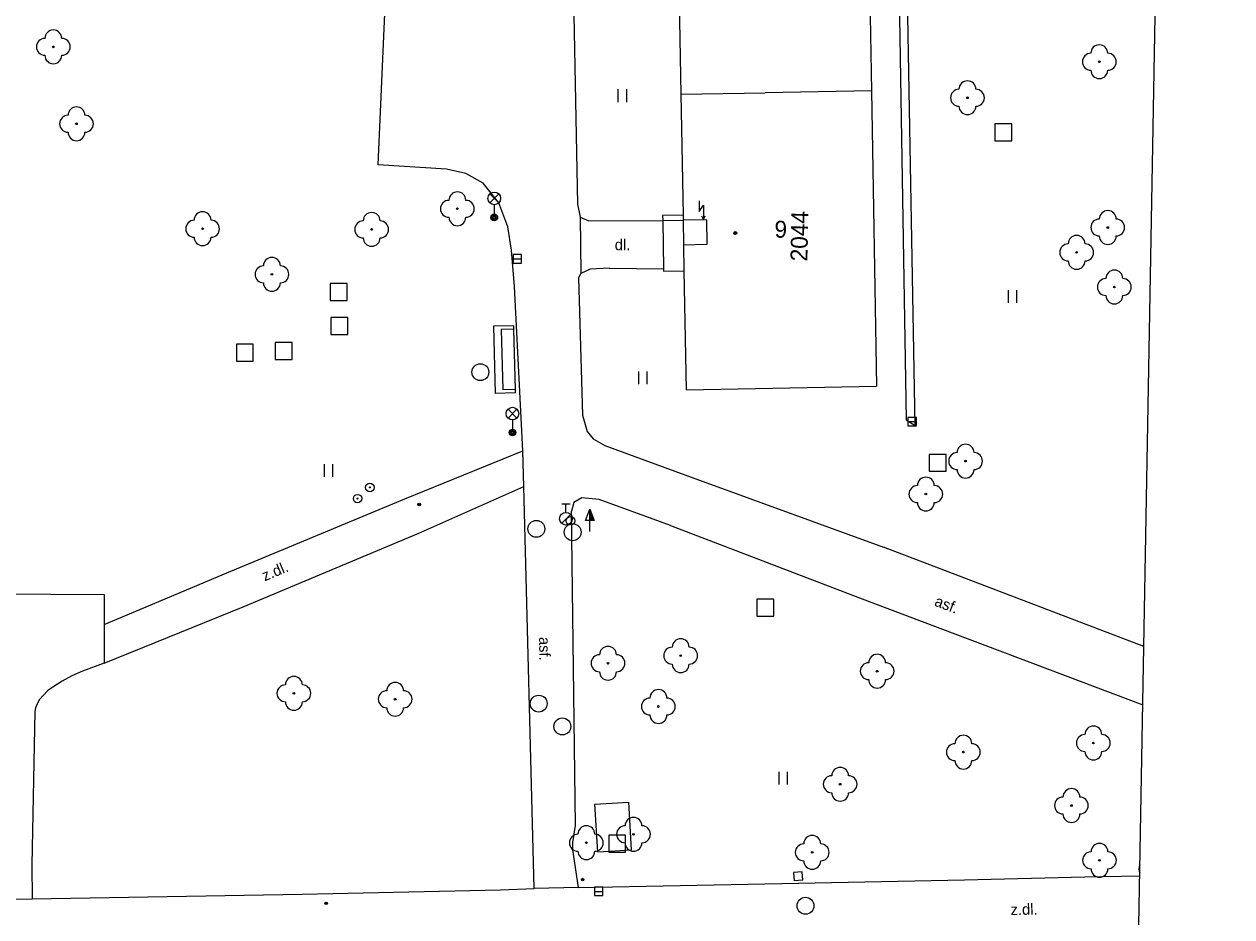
# Model space of a CAD drawing. Extents: x -641829 to -641525, y -1114855 to -1114359.
# Drawn here: x -641596.7 to -641525.3, y -1114670.9 to -1114618.1 of the extents above; entities that cross this region are included whole.
import ezdxf

# ---------------------------------------------------------------- set-up
doc = ezdxf.new("R2010")
doc.units = 0
for name, color, linetype in [('Vrstva 1', 7, 'Continuous'), ('Vrstva 10', 7, 'Continuous'), ('Vrstva 11', 7, 'Continuous'), ('Vrstva 20', 7, 'Continuous'), ('Vrstva 22', 7, 'Continuous'), ('Vrstva 24', 7, 'Continuous'), ('Vrstva 25', 7, 'Continuous'), ('Vrstva 26', 7, 'Continuous'), ('Vrstva 27', 7, 'Continuous'), ('Vrstva 28', 7, 'Continuous'), ('Vrstva 33', 7, 'Continuous'), ('Vrstva 36', 7, 'Continuous'), ('Vrstva 39', 7, 'Continuous'), ('Vrstva 40', 7, 'Continuous'), ('Vrstva 46', 7, 'Continuous'), ('Vrstva 47', 7, 'Continuous'), ('Vrstva 5', 7, 'Continuous')]:
    doc.layers.add(name, color=color, linetype=linetype)

msp = doc.modelspace()

# ---------------------------------------------------------------- linework, layer by layer
at = {"layer": 'Vrstva 1'}
msp.add_line((-641533.66, -1114832.21), (-641525.3, -1114362.64), dxfattribs=at)
at = {"layer": 'Vrstva 10'}
for p, q in [((-641564.29, -1114614.35), (-641564.01, -1114628.78)), ((-641575.8, -1114626.45), (-641575.4, -1114617.49)), ((-641571.76, -1114626.7), (-641575.8, -1114626.45)), ((-641570.6, -1114626.96), (-641571.76, -1114626.7)), ((-641569.59, -1114627.54), (-641570.6, -1114626.96)), ((-641568.65, -1114628.7), (-641569.59, -1114627.54)), ((-641568.13, -1114630.12), (-641568.65, -1114628.7)), ((-641564.01, -1114628.78), (-641563.85, -1114629.54)), ((-641563.85, -1114629.54), (-641563.81, -1114632.87)), ((-641567.91, -1114631.49), (-641568.13, -1114630.12)), ((-641567.73, -1114633.65), (-641567.91, -1114631.49)), ((-641563.81, -1114632.87), (-641563.94, -1114633.13)), ((-641563.94, -1114633.13), (-641563.71, -1114641.27)), ((-641567.24, -1114643.38), (-641567.73, -1114633.65)), ((-641563.71, -1114641.27), (-641563.43, -1114642.22)), ((-641563.43, -1114642.22), (-641563.07, -1114642.67)), ((-641563.07, -1114642.67), (-641562.38, -1114643.06)), ((-641562.38, -1114643.06), (-641557.66, -1114644.8)), ((-641567.17, -1114645.49), (-641567.24, -1114643.38)), ((-641557.66, -1114644.8), (-641545.9, -1114649.08)), ((-641566.56, -1114669.27), (-641567.17, -1114645.49)), ((-641564.23, -1114646.43), (-641564.35, -1114646.95)), ((-641563.74, -1114646.15), (-641564.23, -1114646.43)), ((-641562.73, -1114646.25), (-641563.74, -1114646.15)), ((-641558.5, -1114647.79), (-641562.73, -1114646.25)), ((-641564.12, -1114665.54), (-641564.35, -1114646.95)), ((-641558.5, -1114647.79), (-641547.33, -1114652.07)), ((-641530.504, -1114654.95), (-641545.9, -1114649.08)), ((-641547.33, -1114652.07), (-641530.566, -1114658.41)), ((-641564.28, -1114666.55), (-641564.12, -1114665.54)), ((-641564.28, -1114666.99), (-641564.28, -1114666.55)), ((-641563.94, -1114669.21), (-641564.28, -1114666.99)), ((-641563.94, -1114669.21), (-641566.56, -1114669.27))]:
    msp.add_line(p, q, dxfattribs=at)
at = {"layer": 'Vrstva 11'}
for p, q in [((-641545.19, -1114602.86), (-641544.57, -1114641.53)), ((-641544.03, -1114641.87), (-641544.73, -1114603.5)), ((-641563.85, -1114629.54), (-641563.33, -1114629.76)), ((-641557.76, -1114629.42), (-641558.97, -1114629.45)), ((-641558.97, -1114629.45), (-641558.96, -1114629.75)), ((-641563.33, -1114629.76), (-641558.96, -1114629.75)), ((-641558.96, -1114629.75), (-641557.76, -1114629.73)), ((-641558.96, -1114629.75), (-641558.91, -1114632.61)), ((-641563.25, -1114632.62), (-641563.81, -1114632.87)), ((-641562.12, -1114632.57), (-641563.25, -1114632.62)), ((-641562.12, -1114632.57), (-641558.91, -1114632.61)), ((-641558.91, -1114632.61), (-641558.91, -1114632.75)), ((-641558.91, -1114632.75), (-641557.71, -1114632.73)), ((-641567.77, -1114635.97), (-641568.97, -1114636)), ((-641568.97, -1114636), (-641568.88, -1114639.97)), ((-641567.77, -1114636.17), (-641567.77, -1114635.97)), ((-641567.77, -1114636.17), (-641568.52, -1114636.19)), ((-641568.52, -1114636.19), (-641568.43, -1114639.76)), ((-641567.68, -1114639.74), (-641567.77, -1114636.17)), ((-641567.68, -1114639.94), (-641568.88, -1114639.97)), ((-641567.68, -1114639.74), (-641568.43, -1114639.76)), ((-641567.68, -1114639.94), (-641567.68, -1114639.74)), ((-641544.57, -1114641.53), (-641544.03, -1114641.87)), ((-641574.22, -1114646.22), (-641567.24, -1114643.38)), ((-641573.38, -1114648.25), (-641567.17, -1114645.49)), ((-641584.64, -1114650.55), (-641574.22, -1114646.22)), ((-641583.78, -1114652.6), (-641573.38, -1114648.25)), ((-641592.01, -1114653.64), (-641584.64, -1114650.55)), ((-641607.69, -1114651.77), (-641592.01, -1114651.88)), ((-641592.01, -1114651.88), (-641592, -1114655.94)), ((-641592, -1114655.94), (-641583.78, -1114652.6)), ((-641592, -1114655.94), (-641593.28, -1114656.41)), ((-641593.91, -1114656.69), (-641594.48, -1114657)), ((-641593.28, -1114656.41), (-641593.91, -1114656.69)), ((-641595.04, -1114657.35), (-641595.33, -1114657.56)), ((-641594.48, -1114657), (-641595.04, -1114657.35)), ((-641595.82, -1114658.09), (-641595.95, -1114658.31)), ((-641595.61, -1114657.84), (-641595.82, -1114658.09)), ((-641595.33, -1114657.56), (-641595.61, -1114657.84)), ((-641596.11, -1114658.8), (-641596.29, -1114667.87)), ((-641596.06, -1114658.57), (-641596.11, -1114658.8)), ((-641595.95, -1114658.31), (-641596.06, -1114658.57)), ((-641562.97, -1114664.27), (-641560.97, -1114664.16)), ((-641562.81, -1114667.1), (-641562.97, -1114664.27)), ((-641560.81, -1114666.99), (-641560.97, -1114664.16)), ((-641562.81, -1114667.1), (-641560.81, -1114666.99)), ((-641596.29, -1114667.87), (-641596.27, -1114669.88)), ((-641551.91, -1114668.97), (-641541.12, -1114668.75)), ((-641550.72, -1114668.29), (-641551.23, -1114668.33)), ((-641551.23, -1114668.33), (-641551.18, -1114668.82)), ((-641550.68, -1114668.77), (-641551.18, -1114668.82)), ((-641550.68, -1114668.77), (-641550.72, -1114668.29)), ((-641541.12, -1114668.75), (-641534, -1114668.58)), ((-641534, -1114668.58), (-641530.746, -1114668.511)), ((-641580.29, -1114669.6), (-641568.55, -1114669.34)), ((-641568.55, -1114669.34), (-641566.56, -1114669.27)), ((-641563.94, -1114669.21), (-641551.91, -1114668.97)), ((-641600.06, -1114669.96), (-641596.27, -1114669.88)), ((-641596.27, -1114669.88), (-641580.29, -1114669.6))]:
    msp.add_line(p, q, dxfattribs=at)
at = {"layer": 'Vrstva 20'}
for centre, radius in [((-641573.37, -1114646.55), 0.075), ((-641573.37, -1114646.55), 0.0204), ((-641563.7, -1114668.74), 0.075), ((-641563.7, -1114668.74), 0.0204), ((-641578.87, -1114670.15), 0.075), ((-641578.87, -1114670.15), 0.0204)]:
    msp.add_circle(centre, radius, dxfattribs=at)
at = {"layer": 'Vrstva 22'}
for centre in [(-641595.01, -1114619.47), (-641533.14, -1114620.35), (-641540.94, -1114622.48), (-641593.64, -1114624.02), (-641571.11, -1114629.05), (-641586.18, -1114630.23), (-641576.18, -1114630.27), (-641532.64, -1114630.16), (-641534.48, -1114631.63), (-641582.08, -1114632.93), (-641532.25, -1114633.68), (-641541.05, -1114643.98), (-641543.4, -1114645.93), (-641562.2, -1114655.94), (-641557.9, -1114655.49), (-641546.28, -1114656.41), (-641580.78, -1114657.72), (-641574.79, -1114658.07), (-641559.22, -1114658.5), (-641533.49, -1114660.66), (-641541.18, -1114661.2), (-641548.47, -1114663.1), (-641534.79, -1114664.36), (-641560.69, -1114666.06), (-641563.48, -1114666.56), (-641550.12, -1114667.13), (-641533.13, -1114667.6)]:
    msp.add_circle(centre, 0.05, dxfattribs=at)
for centre, start, end in [((-641595.01, -1114618.97), 0, 180), ((-641595.51, -1114619.47), 90, 270), ((-641594.51, -1114619.47), 270, 90), ((-641533.14, -1114619.85), 0, 180), ((-641595.01, -1114619.97), 180, 0), ((-641533.64, -1114620.35), 90, 270), ((-641532.64, -1114620.35), 270, 90), ((-641533.14, -1114620.85), 180, 0), ((-641540.94, -1114621.98), 0, 180), ((-641541.44, -1114622.48), 90, 270), ((-641540.44, -1114622.48), 270, 90), ((-641593.64, -1114623.52), 0, 180), ((-641540.94, -1114622.98), 180, 0), ((-641594.14, -1114624.02), 90, 270), ((-641593.14, -1114624.02), 270, 90), ((-641593.64, -1114624.52), 180, 0), ((-641571.11, -1114628.55), 0, 180), ((-641571.61, -1114629.05), 90, 270), ((-641570.61, -1114629.05), 270, 90), ((-641586.18, -1114629.73), 0, 180), ((-641576.18, -1114629.77), 0, 180), ((-641571.11, -1114629.55), 180, 0), ((-641532.64, -1114629.66), 0, 180), ((-641586.68, -1114630.23), 90, 270), ((-641585.68, -1114630.23), 270, 90), ((-641576.68, -1114630.27), 90, 270), ((-641575.68, -1114630.27), 270, 90), ((-641533.14, -1114630.16), 90, 270), ((-641532.14, -1114630.16), 270, 90), ((-641586.18, -1114630.73), 180, 0), ((-641576.18, -1114630.77), 180, 0), ((-641534.48, -1114631.13), 0, 180), ((-641532.64, -1114630.66), 180, 0), ((-641534.98, -1114631.63), 90, 270), ((-641533.98, -1114631.63), 270, 90), ((-641582.58, -1114632.93), 90, 270), ((-641582.08, -1114632.43), 0, 180), ((-641581.58, -1114632.93), 270, 90), ((-641534.48, -1114632.13), 180, 0), ((-641532.25, -1114633.18), 0, 180), ((-641582.08, -1114633.43), 180, 0), ((-641532.75, -1114633.68), 90, 270), ((-641531.75, -1114633.68), 270, 90), ((-641532.25, -1114634.18), 180, 0), ((-641541.05, -1114643.48), 0, 180), ((-641541.55, -1114643.98), 90, 270), ((-641540.55, -1114643.98), 270, 90), ((-641541.05, -1114644.48), 180, 0), ((-641543.4, -1114645.43), 0, 180), ((-641543.9, -1114645.93), 90, 270), ((-641542.9, -1114645.93), 270, 90), ((-641543.4, -1114646.43), 180, 0), ((-641557.9, -1114654.99), 0, 180), ((-641562.2, -1114655.44), 0, 180), ((-641558.4, -1114655.49), 90, 270), ((-641557.4, -1114655.49), 270, 90), ((-641562.7, -1114655.94), 90, 270), ((-641561.7, -1114655.94), 270, 90), ((-641557.9, -1114655.99), 180, 0), ((-641546.78, -1114656.41), 90, 270), ((-641546.28, -1114655.91), 0, 180), ((-641545.78, -1114656.41), 270, 90), ((-641580.78, -1114657.22), 0, 180), ((-641562.2, -1114656.44), 180, 0), ((-641581.28, -1114657.72), 90, 270), ((-641580.28, -1114657.72), 270, 90), ((-641574.79, -1114657.57), 0, 180), ((-641546.28, -1114656.91), 180, 0), ((-641575.29, -1114658.07), 90, 270), ((-641574.29, -1114658.07), 270, 90), ((-641559.72, -1114658.5), 90, 270), ((-641559.22, -1114658), 0, 180), ((-641558.72, -1114658.5), 270, 90), ((-641580.78, -1114658.22), 180, 0), ((-641574.79, -1114658.57), 180, 0), ((-641559.22, -1114659), 180, 0), ((-641541.18, -1114660.7), 0, 180), ((-641533.99, -1114660.66), 90, 270), ((-641533.49, -1114660.16), 0, 180), ((-641532.99, -1114660.66), 270, 90), ((-641541.68, -1114661.2), 90, 270), ((-641540.68, -1114661.2), 270, 90), ((-641541.18, -1114661.7), 180, 0), ((-641533.49, -1114661.16), 180, 0), ((-641548.47, -1114662.6), 0, 180), ((-641548.97, -1114663.1), 90, 270), ((-641547.97, -1114663.1), 270, 90), ((-641548.47, -1114663.6), 180, 0), ((-641535.29, -1114664.36), 90, 270), ((-641534.79, -1114663.86), 0, 180), ((-641534.29, -1114664.36), 270, 90), ((-641560.69, -1114665.56), 0, 180), ((-641534.79, -1114664.86), 180, 0), ((-641563.48, -1114666.06), 0, 180), ((-641561.19, -1114666.06), 90, 270), ((-641560.19, -1114666.06), 270, 90), ((-641563.98, -1114666.56), 90, 270), ((-641562.98, -1114666.56), 270, 90), ((-641560.69, -1114666.56), 180, 0), ((-641550.62, -1114667.13), 90, 270), ((-641550.12, -1114666.63), 0, 180), ((-641549.62, -1114667.13), 270, 90), ((-641533.13, -1114667.1), 0, 180), ((-641563.48, -1114667.06), 180, 0), ((-641533.63, -1114667.6), 90, 270), ((-641532.63, -1114667.6), 270, 90), ((-641550.12, -1114667.63), 180, 0), ((-641533.13, -1114668.1), 180, 0), ((-641530.3, -1114668.12), 150.27466, 207.68543)]:
    msp.add_arc(centre, 0.5, start, end, dxfattribs=at)
at = {"layer": 'Vrstva 24'}
for p, q in [((-641556.81, -1114628.584), (-641556.81, -1114629.21)), ((-641556.81, -1114629.21), (-641556.56, -1114628.835)), ((-641556.56, -1114628.835), (-641556.56, -1114629.71)), ((-641556.67, -1114629.465), (-641556.56, -1114629.71)), ((-641556.56, -1114629.71), (-641556.45, -1114629.465))]:
    msp.add_line(p, q, dxfattribs=at)
at = {"layer": 'Vrstva 25'}
for p, q in [((-641563.522, -1114647.498), (-641563.27, -1114646.824)), ((-641563.27, -1114647.498), (-641563.522, -1114647.498)), ((-641563.27, -1114648.15), (-641563.27, -1114647.5))]:
    msp.add_line(p, q, dxfattribs=at)
for points in [[(-641563.02, -1114647.5), (-641563.27, -1114647.5), (-641563.27, -1114646.824), (-641563.27, -1114646.824)], [(-641563.077, -1114647.46), (-641563.23, -1114647.46), (-641563.23, -1114647.047)], [(-641563.135, -1114647.42), (-641563.19, -1114647.42), (-641563.19, -1114647.271)]]:
    msp.add_lwpolyline(points, close=True, dxfattribs=at)
for centre, radius in [((-641576.29, -1114645.54), 0.25), ((-641577.01, -1114646.2), 0.25), ((-641576.29, -1114645.54), 0.0303), ((-641577.01, -1114646.2), 0.0303)]:
    msp.add_circle(centre, radius, dxfattribs=at)
at = {"layer": 'Vrstva 26'}
for points in [[(-641539.32, -1114625.02), (-641538.32, -1114625.02), (-641538.32, -1114624.02), (-641539.32, -1114624.02)], [(-641578.63, -1114634.48), (-641577.63, -1114634.48), (-641577.63, -1114633.48), (-641578.63, -1114633.48)], [(-641578.59, -1114636.48), (-641577.59, -1114636.48), (-641577.59, -1114635.48), (-641578.59, -1114635.48)], [(-641584.18, -1114638.06), (-641583.18, -1114638.06), (-641583.18, -1114637.06), (-641584.18, -1114637.06)], [(-641581.88, -1114637.96), (-641580.88, -1114637.96), (-641580.88, -1114636.96), (-641581.88, -1114636.96)], [(-641543.2, -1114644.58), (-641542.2, -1114644.58), (-641542.2, -1114643.58), (-641543.2, -1114643.58)], [(-641553.4, -1114653.15), (-641552.4, -1114653.15), (-641552.4, -1114652.15), (-641553.4, -1114652.15)], [(-641562.16, -1114667.12), (-641561.16, -1114667.12), (-641561.16, -1114666.12), (-641562.16, -1114666.12)]]:
    msp.add_lwpolyline(points, close=True, dxfattribs=at)
at = {"layer": 'Vrstva 27'}
for p, q in [((-641567.81, -1114632.01), (-641567.31, -1114632.01)), ((-641544.46, -1114641.64), (-641543.96, -1114641.64)), ((-641563, -1114669.44), (-641562.5, -1114669.44))]:
    msp.add_line(p, q, dxfattribs=at)
for points in [[(-641567.81, -1114632.26), (-641567.31, -1114632.26), (-641567.31, -1114631.76), (-641567.81, -1114631.76)], [(-641544.46, -1114641.89), (-641543.96, -1114641.89), (-641543.96, -1114641.39), (-641544.46, -1114641.39)], [(-641563, -1114669.69), (-641562.5, -1114669.69), (-641562.5, -1114669.19), (-641563, -1114669.19)]]:
    msp.add_lwpolyline(points, close=True, dxfattribs=at)
for centre in [(-641569.75, -1114638.72), (-641566.44, -1114647.99), (-641564.29, -1114648.19), (-641566.3, -1114658.33), (-641564.9, -1114659.68), (-641550.52, -1114670.29)]:
    msp.add_circle(centre, 0.5, dxfattribs=at)
at = {"layer": 'Vrstva 28'}
for p, q in [((-641564.94, -1114646.515), (-641564.44, -1114646.515)), ((-641564.69, -1114647.015), (-641564.69, -1114646.515)), ((-641564.948, -1114647.662), (-641564.418, -1114647.132))]:
    msp.add_line(p, q, dxfattribs=at)
for centre, radius in [((-641564.69, -1114647.39), 0.375), ((-641564.42, -1114647.51), 0.25)]:
    msp.add_circle(centre, radius, dxfattribs=at)
at = {"layer": 'Vrstva 33'}
for p, q in [((-641569.194, -1114628.7), (-641568.666, -1114628.17)), ((-641569.194, -1114628.17), (-641568.666, -1114628.7)), ((-641568.93, -1114628.81), (-641568.93, -1114629.56)), ((-641568.115, -1114641.43), (-641567.585, -1114640.9)), ((-641568.115, -1114640.9), (-641567.585, -1114641.43)), ((-641567.85, -1114641.54), (-641567.85, -1114642.29))]:
    msp.add_line(p, q, dxfattribs=at)
for centre, radius in [((-641568.93, -1114628.435), 0.375), ((-641568.93, -1114629.56), 0.2), ((-641568.93, -1114629.56), 0.145), ((-641568.93, -1114629.56), 0.0876), ((-641567.85, -1114641.165), 0.375), ((-641567.85, -1114642.29), 0.2), ((-641567.85, -1114642.29), 0.145), ((-641567.85, -1114642.29), 0.0876)]:
    msp.add_circle(centre, radius, dxfattribs=at)
at = {"layer": 'Vrstva 36'}
for p, q in [((-641561.594, -1114622.734), (-641561.594, -1114621.982)), ((-641561.094, -1114622.734), (-641561.094, -1114621.982)), ((-641538.514, -1114634.614), (-641538.514, -1114633.862)), ((-641538.014, -1114634.614), (-641538.014, -1114633.862)), ((-641560.384, -1114639.424), (-641560.384, -1114638.672)), ((-641559.884, -1114639.424), (-641559.884, -1114638.672)), ((-641578.974, -1114644.902), (-641578.974, -1114644.154)), ((-641578.474, -1114644.902), (-641578.474, -1114644.154)), ((-641552.074, -1114663.112), (-641552.074, -1114662.364)), ((-641551.574, -1114663.112), (-641551.574, -1114662.364))]:
    msp.add_line(p, q, dxfattribs=at)
at = {"layer": 'Vrstva 39'}
for radius in [0.09, 0.0398]:
    msp.add_circle((-641554.67, -1114630.49), radius, dxfattribs=at)
at = {"layer": 'Vrstva 5'}
for p, q in [((-641546.94, -1114602.5), (-641546.61, -1114622.07)), ((-641557.9, -1114622.27), (-641552.9, -1114622.18)), ((-641557.9, -1114622.27), (-641557.76, -1114629.42)), ((-641546.61, -1114622.07), (-641552.9, -1114622.18)), ((-641546.61, -1114622.07), (-641546.31, -1114639.55)), ((-641557.76, -1114629.42), (-641557.76, -1114629.73)), ((-641556.36, -1114629.71), (-641557.76, -1114629.73)), ((-641557.76, -1114629.73), (-641557.74, -1114631.18)), ((-641556.34, -1114631.15), (-641556.36, -1114629.71)), ((-641557.74, -1114631.18), (-641556.34, -1114631.15)), ((-641557.74, -1114631.18), (-641557.71, -1114632.73)), ((-641557.71, -1114632.73), (-641557.58, -1114639.77)), ((-641557.58, -1114639.77), (-641546.31, -1114639.55))]:
    msp.add_line(p, q, dxfattribs=at)
msp.add_lwpolyline([(-641558.08, -1114612), (-641558.06, -1114613.53), (-641557.9, -1114622.27)], dxfattribs=at)

# ---------------------------------------------------------------- texts
at = {"layer": 'Vrstva 40'}
msp.add_text('dl.', height=0.65, dxfattribs=at).set_placement((-641561.8, -1114631.5))
for s, height, rotation, p in [('z.dl.', 0.6499, 22.69806, (-641582.51, -1114651.1)), ('asf.', 0.65, 339.2852, (-641542.94, -1114652.52)), ('asf.', 0.65, 271.03481, (-641566.28, -1114654.39)), ('z.dl.', 0.65, 1.10826, (-641538.38, -1114670.84))]:
    msp.add_text(s, height=height, rotation=rotation, dxfattribs=at).set_placement(p)
at = {"layer": 'Vrstva 46'}
msp.add_text('9', height=1, dxfattribs=at).set_placement((-641552.35, -1114630.76))
at = {"layer": 'Vrstva 47'}
msp.add_text('2044', height=1, rotation=88.81283, dxfattribs=at).set_placement((-641550.41, -1114632.17))

doc.saveas('drawing.dxf')
